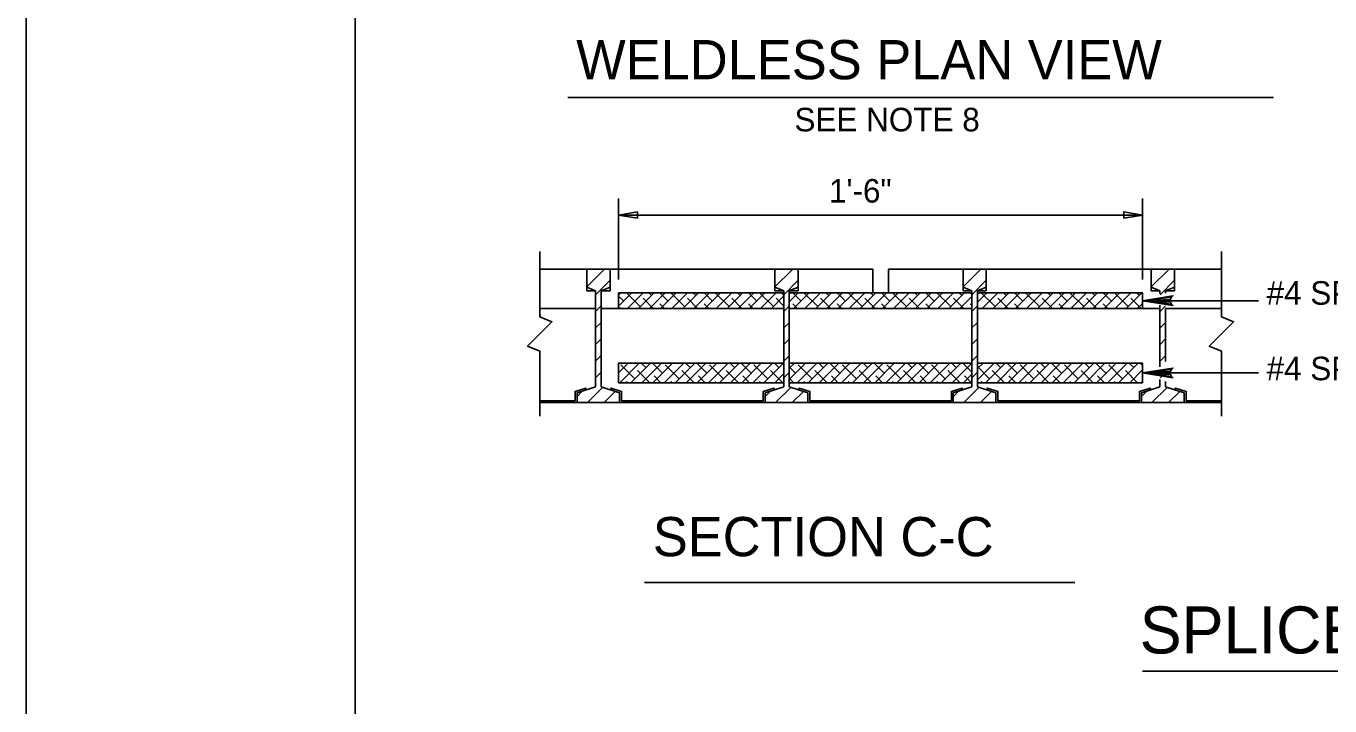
# Model space of a CAD drawing. Extents: x -24512 to -22484, y 4569 to 6351.
# Drawn here: x -24179.8 to -24013.4, y 5326.6 to 5413.3 of the extents above; entities that cross this region are included whole.
import ezdxf

# ---------------------------------------------------------------- set-up
doc = ezdxf.new("R2010")
doc.units = 0
for name, color, linetype in [('10', 7, 'Continuous'), ('2', 7, 'Continuous'), ('3', 7, 'Continuous'), ('4', 7, 'Continuous'), ('8', 7, 'Continuous'), ('9', 7, 'Continuous'), ('PLT-BNDY', 7, 'Continuous')]:
    doc.layers.add(name, color=color, linetype=linetype)

# ---------------------------------------------------------------- blocks, each defined once
blk = doc.blocks.new('SYM029')
at = {"layer": '3'}
for p, q in [((45.29725, 11.51025), (45.748875, 11.96175)), ((45.29725, 11.937875), (45.32125, 11.96175)), ((45.52425, 11.3095), (45.8965, 11.68175)), ((45.52425, 10.881875), (45.6695, 11.027)), ((45.52425, 10.454125), (45.6695, 10.599375)), ((45.52425, 10.0265), (45.6695, 10.171625)), ((45.52425, 9.59875), (45.6695, 9.744)), ((45.52425, 9.171125), (45.6695, 9.31625)), ((45.04875, 8.6955), (45.18175, 8.8285)), ((45.31525, 8.534375), (45.7065, 8.925625)), ((45.743, 8.534375), (46.031, 8.8225))]:
    blk.add_line(p, q, dxfattribs=at)
blk = doc.blocks.new('SYM030')
at = {"layer": '3'}
for p, q in [((177.0355, 162.209125), (177.2735, 162.447125)), ((177.489125, 162.0925), (177.134375, 162.447125)), ((177.155375, 162.043875), (177.558625, 162.447125)), ((177.4405, 162.043875), (177.84375, 162.447125)), ((177.82275, 162.043875), (177.560375, 162.30625)), ((177.77425, 162.3775), (177.704625, 162.447125)), ((177.725625, 162.043875), (178.128875, 162.447125)), ((178.201875, 162.235), (177.98975, 162.447125)), ((178.01075, 162.043875), (178.414, 162.447125)), ((178.629625, 162.0925), (178.274875, 162.447125)), ((178.295875, 162.043875), (178.699125, 162.447125)), ((178.581, 162.043875), (178.98425, 162.447125)), ((178.96325, 162.043875), (178.700875, 162.30625)), ((178.91475, 162.3775), (178.845125, 162.447125)), ((178.866125, 162.043875), (179.269375, 162.447125)), ((179.342375, 162.235), (179.13025, 162.447125)), ((179.15125, 162.043875), (179.5545, 162.447125)), ((179.770125, 162.0925), (179.415375, 162.447125)), ((179.436375, 162.043875), (179.839625, 162.447125)), ((179.7215, 162.043875), (180.12475, 162.447125)), ((180.10375, 162.043875), (179.841375, 162.30625)), ((180.05525, 162.3775), (179.985625, 162.447125)), ((180.006625, 162.043875), (180.409875, 162.447125)), ((180.482875, 162.235), (180.27075, 162.447125)), ((180.29175, 162.043875), (180.695, 162.447125)), ((180.910625, 162.0925), (180.555875, 162.447125)), ((180.576875, 162.043875), (180.980125, 162.447125)), ((180.862, 162.043875), (181.26525, 162.447125)), ((181.24425, 162.043875), (180.981875, 162.30625)), ((181.19575, 162.3775), (181.126125, 162.447125)), ((177.061375, 162.235), (177.0355, 162.260875)), ((178.107875, 162.043875), (177.988, 162.16375)), ((179.248375, 162.043875), (179.1285, 162.16375)), ((180.388875, 162.043875), (180.269, 162.16375)), ((181.147125, 162.043875), (181.279625, 162.176375))]:
    blk.add_line(p, q, dxfattribs=at)
blk = doc.blocks.new('SYM031')
at = {"layer": '3'}
for p, q in [((172.19675, 162.2175), (172.4265, 162.447125)), ((172.499375, 162.235), (172.28725, 162.447125)), ((172.308375, 162.043875), (172.711625, 162.447125)), ((172.927125, 162.0925), (172.572375, 162.447125)), ((172.5935, 162.043875), (172.996625, 162.447125)), ((172.878625, 162.043875), (173.28175, 162.447125)), ((173.26075, 162.043875), (172.998375, 162.30625)), ((173.21225, 162.3775), (173.142625, 162.447125)), ((173.16375, 162.043875), (173.566875, 162.447125)), ((173.639875, 162.235), (173.42775, 162.447125)), ((173.448875, 162.043875), (173.852, 162.447125)), ((174.067625, 162.0925), (173.712875, 162.447125)), ((173.734, 162.043875), (174.137125, 162.447125)), ((174.019125, 162.043875), (174.42225, 162.447125)), ((174.40125, 162.043875), (174.138875, 162.30625)), ((174.35275, 162.3775), (174.283125, 162.447125)), ((174.30425, 162.043875), (174.707375, 162.447125)), ((174.780375, 162.235), (174.56825, 162.447125)), ((174.589375, 162.043875), (174.9925, 162.447125)), ((175.208125, 162.0925), (174.853375, 162.447125)), ((174.8745, 162.043875), (175.277625, 162.447125)), ((175.159625, 162.043875), (175.56275, 162.447125)), ((175.54175, 162.043875), (175.279375, 162.30625)), ((175.49325, 162.3775), (175.423625, 162.447125)), ((175.44475, 162.043875), (175.847875, 162.447125)), ((175.920875, 162.235), (175.70875, 162.447125)), ((175.729875, 162.043875), (176.133, 162.447125)), ((176.348625, 162.0925), (175.993875, 162.447125)), ((176.015, 162.043875), (176.418125, 162.447125)), ((176.3, 162.043875), (176.70325, 162.447125)), ((176.68225, 162.043875), (176.419875, 162.30625)), ((176.63375, 162.3775), (176.564125, 162.447125)), ((176.585125, 162.043875), (176.89025, 162.349)), ((176.89025, 162.406125), (176.84925, 162.447125)), ((172.405375, 162.043875), (172.285625, 162.16375)), ((173.545875, 162.043875), (173.426125, 162.16375)), ((174.686375, 162.043875), (174.566625, 162.16375)), ((175.826875, 162.043875), (175.707125, 162.16375)), ((176.89025, 162.121), (176.8475, 162.16375)), ((176.87025, 162.043875), (176.89025, 162.063875))]:
    blk.add_line(p, q, dxfattribs=at)
blk = doc.blocks.new('SYM032')
at = {"layer": '3'}
for p, q in [((167.8075, 162.105), (168.149625, 162.447125)), ((167.8075, 162.390125), (167.8645, 162.447125)), ((167.9375, 162.235), (167.8075, 162.365)), ((168.365125, 162.0925), (168.0105, 162.447125)), ((168.0315, 162.043875), (168.43475, 162.447125)), ((168.316625, 162.043875), (168.719875, 162.447125)), ((168.69875, 162.043875), (168.436375, 162.30625)), ((168.65025, 162.3775), (168.58075, 162.447125)), ((168.60175, 162.043875), (169.005, 162.447125)), ((169.078, 162.235), (168.865875, 162.447125)), ((168.886875, 162.043875), (169.290125, 162.447125)), ((169.505625, 162.0925), (169.151, 162.447125)), ((169.172, 162.043875), (169.57525, 162.447125)), ((169.457125, 162.043875), (169.860375, 162.447125)), ((169.83925, 162.043875), (169.576875, 162.30625)), ((169.79075, 162.3775), (169.72125, 162.447125)), ((169.74225, 162.043875), (170.1455, 162.447125)), ((170.2185, 162.235), (170.006375, 162.447125)), ((170.027375, 162.043875), (170.430625, 162.447125)), ((170.646125, 162.0925), (170.2915, 162.447125)), ((170.3125, 162.043875), (170.71575, 162.447125)), ((170.597625, 162.043875), (171.000875, 162.447125)), ((170.97975, 162.043875), (170.717375, 162.30625)), ((170.93125, 162.3775), (170.861625, 162.447125)), ((170.88275, 162.043875), (171.286, 162.447125)), ((171.359, 162.235), (171.14675, 162.447125)), ((171.167875, 162.043875), (171.571125, 162.447125)), ((171.786625, 162.0925), (171.431875, 162.447125)), ((171.453, 162.043875), (171.85625, 162.447125)), ((171.738125, 162.043875), (172.051625, 162.357375)), ((172.051625, 162.112625), (171.857875, 162.30625)), ((172.051625, 162.39775), (172.002125, 162.447125)), ((167.843375, 162.043875), (167.8075, 162.079875)), ((168.983875, 162.043875), (168.864125, 162.16375)), ((170.124375, 162.043875), (170.004625, 162.16375)), ((171.264875, 162.043875), (171.145125, 162.16375)), ((172.02325, 162.043875), (172.051625, 162.07225))]:
    blk.add_line(p, q, dxfattribs=at)
blk = doc.blocks.new('SYM033')
at = {"layer": '3'}
for p, q in [((167.8075, 160.39425), (168.0545, 160.64125)), ((167.8355, 160.13725), (168.339625, 160.64125)), ((168.120625, 160.13725), (168.62475, 160.64125)), ((168.50775, 160.52425), (168.39075, 160.64125)), ((168.40575, 160.13725), (168.909875, 160.64125)), ((168.935375, 160.38175), (168.675875, 160.64125)), ((168.690875, 160.13725), (169.195, 160.64125)), ((168.976, 160.13725), (169.480125, 160.64125)), ((169.261125, 160.13725), (169.76525, 160.64125)), ((169.64825, 160.52425), (169.53125, 160.64125)), ((169.54625, 160.13725), (170.050375, 160.64125)), ((170.075875, 160.38175), (169.816375, 160.64125)), ((169.831375, 160.13725), (170.3355, 160.64125)), ((170.1165, 160.13725), (170.620625, 160.64125)), ((170.401625, 160.13725), (170.90575, 160.64125)), ((170.78875, 160.52425), (170.671625, 160.64125)), ((170.68675, 160.13725), (171.190875, 160.64125)), ((171.216375, 160.38175), (170.95675, 160.64125)), ((170.971875, 160.13725), (171.476, 160.64125)), ((171.257, 160.13725), (171.761125, 160.64125)), ((171.542125, 160.13725), (172.04625, 160.64125)), ((171.929125, 160.52425), (171.812125, 160.64125)), ((168.222625, 160.239125), (167.866125, 160.5955)), ((168.609625, 160.13725), (168.293875, 160.453)), ((168.89475, 160.13725), (168.7215, 160.310375)), ((169.363125, 160.239125), (169.006625, 160.5955)), ((169.750125, 160.13725), (169.434375, 160.453)), ((170.03525, 160.13725), (169.862, 160.310375)), ((170.503625, 160.239125), (170.147125, 160.5955)), ((170.890625, 160.13725), (170.574875, 160.453)), ((171.17575, 160.13725), (171.0025, 160.310375)), ((171.644125, 160.239125), (171.287625, 160.5955)), ((172.031125, 160.13725), (171.715375, 160.453)), ((171.82725, 160.13725), (172.051625, 160.3615)), ((168.039375, 160.13725), (168.00875, 160.167875)), ((169.179875, 160.13725), (169.14925, 160.167875)), ((170.320375, 160.13725), (170.28975, 160.167875)), ((171.460875, 160.13725), (171.43025, 160.167875))]:
    blk.add_line(p, q, dxfattribs=at)
blk = doc.blocks.new('SYM034')
at = {"layer": '3'}
for p, q in [((172.19675, 160.221625), (172.6165, 160.64125)), ((172.19675, 160.50675), (172.331375, 160.64125)), ((172.3975, 160.13725), (172.901625, 160.64125)), ((172.682625, 160.13725), (173.186625, 160.64125)), ((173.069625, 160.52425), (172.952625, 160.64125)), ((172.96775, 160.13725), (173.47175, 160.64125)), ((173.497375, 160.38175), (173.23775, 160.64125)), ((173.252875, 160.13725), (173.756875, 160.64125)), ((173.538, 160.13725), (174.042, 160.64125)), ((173.823125, 160.13725), (174.327125, 160.64125)), ((174.210125, 160.52425), (174.093125, 160.64125)), ((174.10825, 160.13725), (174.61225, 160.64125)), ((174.637875, 160.38175), (174.37825, 160.64125)), ((174.393375, 160.13725), (174.897375, 160.64125)), ((174.6785, 160.13725), (175.1825, 160.64125)), ((174.963625, 160.13725), (175.467625, 160.64125)), ((175.350625, 160.52425), (175.233625, 160.64125)), ((175.24875, 160.13725), (175.75275, 160.64125)), ((175.778375, 160.38175), (175.51875, 160.64125)), ((175.533875, 160.13725), (176.037875, 160.64125)), ((175.819, 160.13725), (176.323, 160.64125)), ((176.104125, 160.13725), (176.608125, 160.64125)), ((176.491125, 160.52425), (176.374125, 160.64125)), ((176.38925, 160.13725), (176.89025, 160.63825)), ((176.89025, 160.41025), (176.65925, 160.64125)), ((172.356875, 160.38175), (172.19675, 160.54175)), ((172.7845, 160.239125), (172.428125, 160.5955)), ((173.171625, 160.13725), (172.855875, 160.453)), ((173.45675, 160.13725), (173.2835, 160.310375)), ((173.925, 160.239125), (173.568625, 160.5955)), ((174.312125, 160.13725), (173.996375, 160.453)), ((174.59725, 160.13725), (174.424, 160.310375)), ((175.0655, 160.239125), (174.709125, 160.5955)), ((175.452625, 160.13725), (175.136875, 160.453)), ((175.737625, 160.13725), (175.5645, 160.310375)), ((176.206, 160.239125), (175.849625, 160.5955)), ((176.593, 160.13725), (176.277375, 160.453)), ((176.674375, 160.13725), (176.89025, 160.353125)), ((176.878125, 160.13725), (176.705, 160.310375)), ((172.31625, 160.13725), (172.19675, 160.256625)), ((172.601375, 160.13725), (172.57075, 160.167875)), ((173.741875, 160.13725), (173.71125, 160.167875)), ((174.882375, 160.13725), (174.85175, 160.167875)), ((176.02275, 160.13725), (175.99225, 160.167875))]:
    blk.add_line(p, q, dxfattribs=at)
blk = doc.blocks.new('SYM035')
at = {"layer": '3'}
for p, q in [((177.0355, 160.21325), (177.4635, 160.64125)), ((177.0355, 160.498375), (177.178375, 160.64125)), ((177.244625, 160.13725), (177.748625, 160.64125)), ((177.631625, 160.52425), (177.514625, 160.64125)), ((177.52975, 160.13725), (178.03375, 160.64125)), ((178.059375, 160.38175), (177.79975, 160.64125)), ((177.814875, 160.13725), (178.318875, 160.64125)), ((178.1, 160.13725), (178.604, 160.64125)), ((178.385125, 160.13725), (178.889125, 160.64125)), ((178.772125, 160.52425), (178.655125, 160.64125)), ((178.67025, 160.13725), (179.17425, 160.64125)), ((179.199875, 160.38175), (178.94025, 160.64125)), ((178.955375, 160.13725), (179.459375, 160.64125)), ((179.2405, 160.13725), (179.7445, 160.64125)), ((179.525625, 160.13725), (180.029625, 160.64125)), ((179.912625, 160.52425), (179.795625, 160.64125)), ((179.81075, 160.13725), (180.31475, 160.64125)), ((180.340375, 160.38175), (180.08075, 160.64125)), ((180.095875, 160.13725), (180.599875, 160.64125)), ((180.381, 160.13725), (180.885, 160.64125)), ((180.666125, 160.13725), (181.170125, 160.64125)), ((181.053125, 160.52425), (180.936125, 160.64125)), ((181.279625, 160.582875), (181.22125, 160.64125)), ((177.3465, 160.239125), (177.0355, 160.55025)), ((177.7335, 160.13725), (177.41775, 160.453)), ((178.018625, 160.13725), (177.8455, 160.310375)), ((178.487, 160.239125), (178.130625, 160.5955)), ((178.874, 160.13725), (178.55825, 160.453)), ((179.159125, 160.13725), (178.986, 160.310375)), ((179.6275, 160.239125), (179.271125, 160.5955)), ((180.0145, 160.13725), (179.69875, 160.453)), ((180.299625, 160.13725), (180.1265, 160.310375)), ((180.768, 160.239125), (180.411625, 160.5955)), ((181.155, 160.13725), (180.83925, 160.453)), ((180.95125, 160.13725), (181.279625, 160.465625)), ((181.279625, 160.29775), (181.267, 160.310375)), ((177.16325, 160.13725), (177.132625, 160.167875)), ((178.30375, 160.13725), (178.273125, 160.167875)), ((179.44425, 160.13725), (179.413625, 160.167875)), ((180.58475, 160.13725), (180.554125, 160.167875)), ((181.236375, 160.13725), (181.279625, 160.1805))]:
    blk.add_line(p, q, dxfattribs=at)

msp = doc.modelspace()

# ---------------------------------------------------------------- linework, layer by layer
at = {"layer": '10'}
for p, q in [((-24020.62, 5404.17), (-24110.63, 5404.17)), ((-24045.99, 5342.35), (-24100.88, 5342.35)), ((-23914.02, 5331.01), (-24037.37, 5331.01))]:
    msp.add_line(p, q, dxfattribs=at)
for points in [[(-24033.66, 5377.8), (-24033.79, 5378.06), (-24037.35, 5378.26), (-24033.66, 5377.8), (-24033.47, 5377.63), (-24037.35, 5378.26), (-24033.8, 5378.43), (-24033.67, 5378.7), (-24037.35, 5378.26), (-24033.47, 5378.88), (-24033.67, 5378.7)], [(-24033.66, 5368.59), (-24033.79, 5368.86), (-24037.35, 5369.05), (-24033.66, 5368.59), (-24033.47, 5368.43), (-24037.35, 5369.05), (-24033.8, 5369.23), (-24033.67, 5369.49), (-24037.35, 5369.05), (-24033.47, 5369.67), (-24033.67, 5369.49)]]:
    msp.add_lwpolyline(points, dxfattribs=at)
at = {"layer": '2'}
msp.add_line((-24137.79, 5178.04), (-24137.79, 5740.63), dxfattribs=at)
at = {"layer": '4'}
for p, q in [((-24108.24, 5382.26), (-24114.23, 5382.26)), ((-24108.24, 5382.26), (-24105.27, 5382.26)), ((-24108.24, 5380), (-24108.24, 5382.26)), ((-24105.27, 5380), (-24105.27, 5382.26)), ((-24084.24, 5382.26), (-24105.27, 5382.26)), ((-24084.24, 5382.26), (-24081.27, 5382.26)), ((-24084.24, 5380), (-24084.24, 5382.26)), ((-24081.27, 5380), (-24081.27, 5382.26)), ((-24071.76, 5382.26), (-24081.27, 5382.26)), ((-24071.76, 5382.26), (-24071.76, 5379.26)), ((-24060.24, 5382.26), (-24069.76, 5382.26)), ((-24069.76, 5382.26), (-24069.76, 5379.26)), ((-24060.24, 5380), (-24060.24, 5382.26)), ((-24060.24, 5382.26), (-24057.27, 5382.26)), ((-24036.24, 5382.26), (-24057.27, 5382.26)), ((-24057.27, 5380), (-24057.27, 5382.26)), ((-24036.24, 5380), (-24036.24, 5382.26)), ((-24036.24, 5382.26), (-24033.27, 5382.26)), ((-24033.27, 5380), (-24033.27, 5382.26)), ((-24027.29, 5382.26), (-24033.27, 5382.26)), ((-24108.24, 5380), (-24107.12, 5379.5)), ((-24108.24, 5380), (-24108.24, 5379.5)), ((-24107.12, 5379.5), (-24108.24, 5379.5)), ((-24107.12, 5367.26), (-24107.12, 5379.5)), ((-24105.27, 5380), (-24106.4, 5379.5)), ((-24106.4, 5367.26), (-24106.4, 5379.5)), ((-24106.4, 5379.5), (-24105.27, 5379.5)), ((-24105.27, 5380), (-24105.27, 5379.5)), ((-24084.24, 5380), (-24083.12, 5379.5)), ((-24084.24, 5380), (-24084.24, 5379.5)), ((-24083.12, 5379.5), (-24084.24, 5379.5)), ((-24083.12, 5367.26), (-24083.12, 5379.5)), ((-24081.27, 5380), (-24082.4, 5379.5)), ((-24082.4, 5367.26), (-24082.4, 5379.5)), ((-24082.4, 5379.5), (-24081.27, 5379.5)), ((-24081.27, 5380), (-24081.27, 5379.5)), ((-24060.24, 5380), (-24059.12, 5379.5)), ((-24060.24, 5380), (-24060.24, 5379.5)), ((-24059.12, 5379.5), (-24060.24, 5379.5)), ((-24059.12, 5367.26), (-24059.12, 5379.5)), ((-24057.27, 5380), (-24058.4, 5379.5)), ((-24058.4, 5379.5), (-24057.27, 5379.5)), ((-24058.4, 5367.26), (-24058.4, 5379.5)), ((-24057.27, 5380), (-24057.27, 5379.5)), ((-24036.24, 5380), (-24036.24, 5379.5)), ((-24036.24, 5380), (-24035.12, 5379.5)), ((-24035.12, 5379.5), (-24036.24, 5379.5)), ((-24035.12, 5379.16), (-24035.12, 5379.5)), ((-24033.27, 5380), (-24034.4, 5379.5)), ((-24034.4, 5379.5), (-24033.27, 5379.5)), ((-24034.4, 5379.21), (-24034.4, 5379.5)), ((-24033.27, 5380), (-24033.27, 5379.5)), ((-24107.12, 5377.26), (-24114.23, 5377.26)), ((-24083.12, 5377.26), (-24106.4, 5377.26)), ((-24071.76, 5377.26), (-24082.4, 5377.26)), ((-24059.12, 5377.26), (-24069.76, 5377.26)), ((-24035.12, 5377.26), (-24058.4, 5377.26)), ((-24035.12, 5369.81), (-24035.12, 5377.67)), ((-24034.4, 5370.49), (-24034.4, 5377.28)), ((-24027.29, 5377.26), (-24034.4, 5377.26)), ((-24107.12, 5367.26), (-24109.47, 5366.51)), ((-24106.4, 5367.26), (-24104.04, 5366.51)), ((-24083.12, 5367.26), (-24085.48, 5366.51)), ((-24082.4, 5367.26), (-24080.04, 5366.51)), ((-24059.12, 5367.26), (-24061.48, 5366.51)), ((-24058.4, 5367.26), (-24056.04, 5366.51)), ((-24035.12, 5367.26), (-24037.48, 5366.51)), ((-24035.12, 5367.26), (-24035.12, 5368.22)), ((-24034.4, 5367.26), (-24034.4, 5367.94)), ((-24034.4, 5367.26), (-24032.04, 5366.51)), ((-24109.47, 5365.26), (-24109.47, 5366.51)), ((-24109.47, 5365.26), (-24104.04, 5365.26)), ((-24104.04, 5365.26), (-24104.04, 5366.51)), ((-24085.48, 5365.26), (-24085.48, 5366.51)), ((-24085.48, 5365.26), (-24080.04, 5365.26)), ((-24080.04, 5365.26), (-24080.04, 5366.51)), ((-24061.48, 5365.26), (-24061.48, 5366.51)), ((-24061.48, 5365.26), (-24056.04, 5365.26)), ((-24056.04, 5365.26), (-24056.04, 5366.51)), ((-24037.48, 5365.26), (-24037.48, 5366.51)), ((-24037.48, 5365.26), (-24032.04, 5365.26)), ((-24032.04, 5365.26), (-24032.04, 5366.51))]:
    msp.add_line(p, q, dxfattribs=at)
for points in [[(-24114.23, 5363.52), (-24114.23, 5371.83), (-24115.78, 5372.48), (-24112.68, 5375.58), (-24114.23, 5376.22), (-24114.23, 5384.54)], [(-24027.29, 5363.52), (-24027.29, 5371.83), (-24028.84, 5372.48), (-24025.73, 5375.58), (-24027.29, 5376.22), (-24027.29, 5384.54)], [(-24114.23, 5365.26), (-24109.47, 5365.26), (-24109.47, 5366.51), (-24108.3, 5366.88), (-24108.37, 5367.12), (-24109.72, 5366.69), (-24109.72, 5365.51), (-24114.23, 5365.51)], [(-24027.29, 5365.51), (-24031.79, 5365.51), (-24031.79, 5366.69), (-24033.14, 5367.12), (-24033.22, 5366.88)], [(-24033.22, 5366.88), (-24032.04, 5366.51), (-24032.04, 5365.26), (-24027.29, 5365.26)]]:
    msp.add_lwpolyline(points, dxfattribs=at)
for points in [[(-24105.22, 5366.88), (-24104.04, 5366.51), (-24104.04, 5365.26), (-24085.48, 5365.26), (-24085.48, 5366.51), (-24084.3, 5366.88), (-24084.37, 5367.12), (-24085.73, 5366.69), (-24085.73, 5365.51), (-24103.79, 5365.51), (-24103.79, 5366.69), (-24105.14, 5367.12)], [(-24081.22, 5366.88), (-24080.04, 5366.51), (-24080.04, 5365.26), (-24061.48, 5365.26), (-24061.48, 5366.51), (-24060.3, 5366.88), (-24060.37, 5367.12), (-24061.73, 5366.69), (-24061.73, 5365.51), (-24079.79, 5365.51), (-24079.79, 5366.69), (-24081.14, 5367.12)], [(-24057.22, 5366.88), (-24056.04, 5366.51), (-24056.04, 5365.26), (-24037.48, 5365.26), (-24037.48, 5366.51), (-24036.3, 5366.88), (-24036.37, 5367.12), (-24037.73, 5366.69), (-24037.73, 5365.51), (-24055.79, 5365.51), (-24055.79, 5366.69), (-24057.14, 5367.12)]]:
    msp.add_lwpolyline(points, close=True, dxfattribs=at)
at = {"layer": '8'}
for p, q in [((-24104.17, 5379.26), (-24083.12, 5379.26)), ((-24104.17, 5377.26), (-24104.17, 5379.26)), ((-24082.4, 5379.26), (-24059.12, 5379.26)), ((-24058.4, 5379.26), (-24037.35, 5379.26)), ((-24037.35, 5377.26), (-24037.35, 5379.26)), ((-24104.17, 5377.26), (-24083.12, 5377.26)), ((-24082.4, 5377.26), (-24059.12, 5377.26)), ((-24058.4, 5377.26), (-24037.35, 5377.26)), ((-24059.12, 5370.3), (-24082.4, 5370.3)), ((-24059.12, 5367.8), (-24082.4, 5367.8))]:
    msp.add_line(p, q, dxfattribs=at)
for points in [[(-24083.12, 5370.3), (-24104.17, 5370.3), (-24104.17, 5367.8), (-24083.12, 5367.8)], [(-24058.4, 5367.8), (-24037.35, 5367.8), (-24037.35, 5370.3), (-24058.4, 5370.3)]]:
    msp.add_lwpolyline(points, dxfattribs=at)
at = {"layer": '9'}
for p, q in [((-24104.17, 5380.96), (-24104.17, 5391.31)), ((-24037.35, 5380.96), (-24037.35, 5391.31)), ((-24037.35, 5389.17), (-24104.17, 5389.17)), ((-24037.35, 5378.26), (-24022.55, 5378.26)), ((-24037.35, 5369.05), (-24022.55, 5369.05))]:
    msp.add_line(p, q, dxfattribs=at)
for points in [[(-24101.77, 5388.77), (-24101.77, 5389.57), (-24104.17, 5389.17)], [(-24039.75, 5388.77), (-24039.75, 5389.57), (-24037.35, 5389.17)]]:
    msp.add_lwpolyline(points, close=True, dxfattribs=at)
at = {"layer": 'PLT-BNDY'}
msp.add_lwpolyline([(-24179.75, 5757.04), (-23338.75, 5757.04), (-23338.75, 5163.04), (-24179.75, 5163.04)], close=True, dxfattribs=at)

# ---------------------------------------------------------------- block references
at = {"layer": '3'}
for name, p, xscale, yscale in [('SYM029', (-24332.91, 5322.93), 4.959842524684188, 4.959842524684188), ('SYM029', (-24308.91, 5322.93), 4.959842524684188, 4.959842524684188), ('SYM029', (-24284.91, 5322.93), 4.959842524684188, 4.959842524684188), ('SYM029', (-24260.91, 5322.93), 4.959842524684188, 4.959842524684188), ('SYM032', (-24936.47, 4573.55), 4.95984251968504, 4.95984251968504), ('SYM031', (-24936.47, 4573.55), 4.95984251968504, 4.95984251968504), ('SYM030', (-24936.47, 4573.55), 4.95984251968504, 4.95984251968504), ('SYM033', (-24936.47, 4573.55), 4.95984251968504, 4.95984251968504), ('SYM034', (-24936.47, 4573.55), 4.95984251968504, 4.95984251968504), ('SYM035', (-24936.47, 4573.55), 4.95984251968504, 4.95984251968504)]:
    msp.add_blockref(name, p, dxfattribs=dict(at, xscale=xscale, yscale=yscale))

# ---------------------------------------------------------------- texts
at = {"layer": '10'}
msp.add_text('SPLICE BETWEEN PANELS', height=6.0008, dxfattribs=at).set_placement((-24037.71, 5333.28))
at = {"layer": '9'}
for s, height, p in [('WELDLESS PLAN VIEW', 5, (-24109.58, 5406.49)), ('SEE NOTE 8', 3, (-24081.74, 5399.85)), ('1\'-6"', 3, (-24077.34, 5390.77)), ('#4 SPLICE BAR', 2.9999, (-24021.52, 5377.75)), ('#4 SPLICE BAR', 2.9999, (-24021.52, 5368.12)), ('SECTION C-C', 5, (-24099.81, 5345.68))]:
    msp.add_text(s, height=height, dxfattribs=at).set_placement(p)

doc.saveas('drawing.dxf')
